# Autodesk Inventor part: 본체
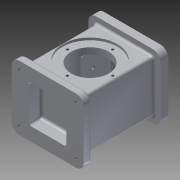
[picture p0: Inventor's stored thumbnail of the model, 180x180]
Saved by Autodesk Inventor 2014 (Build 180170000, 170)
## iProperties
Created: 2017-08
Part Number: 본체
Material: 알루미늄 6061
Document SubType Name: Modeling
Designer: user
Density: 2.71 g/cm^3
Appearance: 알루미늄 - 평지
Mass: 874.034 g
Surface Area: 646.55 cm^2
Volume: 322.522 cm^3
Author: user
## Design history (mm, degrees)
sketch "스케치1"
  geometry: L1 (46, -41)-(-46, -41); L2 (-46, -41)-(-46, 41); L3 (-46, 41)-(46, 41); L4 (46, 41)-(46, -41); L5 (46, -41)-(-46, 41); L6 (-46, -41)-(46, 41); 1 further point
  constraints: 12 end point, 2 midpoint, 2 parallel, 1 horizontal, 1 perpendicular
  dimensions: "d0" = 92 distance of L2.end L3.end; "d1" = 82 distance of L1.end L2.end
extrude "돌출1" new body sketch "스케치1" distance "d2" = 10; taper "d3" = 0 deg
sketch "스케치2"
  geometry: L1 (37, -33)-(-37, -33); L2 (-37, -33)-(-37, 33); L3 (-37, 33)-(37, 33); L4 (37, 33)-(37, -33); L5 (37, -33)-(-37, 33); L6 (-37, -33)-(37, 33); 1 further point
  constraints: 12 end point, 2 midpoint, 2 parallel, 1 horizontal, 1 perpendicular
  dimensions: "d4" = 74 distance of L2.end L3.end; "d5" = 66 distance of L1.end L2.end
extrude "돌출2" join sketch "스케치2" distance "d6" = 98; taper "d7" = 0 deg
sketch "스케치3"
  geometry: L1 (-37, -33)-(37, -33) reference; L2 (37, -33)-(37, 33) reference; L3 (37, 33)-(-37, 33) reference; L4 (-37, 33)-(-37, -33) reference; L5 (46, -41)-(-46, -41); L6 (-46, -41)-(-46, 41); L7 (-46, 41)-(46, 41); L8 (46, 41)-(46, -41); L9 (46, -41)-(-46, 41); L10 (-46, -41)-(46, 41); 1 further point
  constraints: 12 end point, 2 midpoint, 2 parallel, 1 horizontal, 1 perpendicular
  dimensions: "d8" = 92 distance of L6.end L7.end; "d9" = 82 distance of L5.end L6.end
extrude "돌출3" join sketch "스케치3" distance "d10" = 10; taper "d11" = 0 deg
node "작업 평면1"
sketch "스케치4"
  geometry: L1 (74, 0)-(74, -10) reference; L2 (74, -10)-(-8, -10) reference; L3 (-8, -10)-(-8, 0) reference; L4 (-8, 0)-(0, 0) reference; L5 (0, 0)-(0, 88) reference; L6 (0, 88)-(-8, 88) reference; L7 (-8, 88)-(-8, 98) reference; L8 (-8, 98)-(74, 98) reference; L9 (74, 98)-(74, 88) reference; L10 (74, 88)-(66, 88) reference; L11 (66, 88)-(66, 0) reference; L12 (66, 0)-(74, 0) reference; L13 (0, 79)-(3, 79); L14 (3, 79)-(3, 68); L15 (3, 68)-(63, 68); L16 (63, 68)-(63, 79); L17 (63, 79)-(66, 79); L18 (0, 44)-(66, 44); L19 (0, 79)-(0, 44); L20 (66, 79)-(66, 44); 1 further point
  constraints: 16 end point, 4 perpendicular, 3 parallel, 2 collinear, 2 midpoint, 2 point on line
  dimensions: "d12" = 3 distance of L13.start L13.end; "d13" = 3 distance of L16.end L17.end; "d15" = 54 distance from line of L2 L18.start; "d16" = 70 diameter of L13 L18; "d17" = 48 diameter of L15 L18
revolve "회전1" sketch "스케치4" stored, may be unused: angle "d18" = 90 deg
sketch "스케치5"
  geometry: L1 (24, -24)-(-24, -24); L2 (-24, -24)-(-24, 24); L3 (-24, 24)-(24, 24); L4 (24, 24)-(24, -24); L5 (24, -24)-(-24, 24); L6 (-24, -24)-(24, 24); 1 further point
  constraints: 12 end point, 2 midpoint, 2 parallel, 1 horizontal, 1 perpendicular
  dimensions: "d19" = 48 distance of L2.end L3.end; "d20" = 48 distance of L1.end L2.end
extrude "돌출4" cut sketch "스케치5" distance "d21" = 16; taper "d22" = 0 deg
sketch "스케치6"
  geometry: L1 (26, -26)-(-26, -26); L2 (-26, -26)-(-26, 26); L3 (-26, 26)-(26, 26); L4 (26, 26)-(26, -26); L5 (26, -26)-(-26, 26); L6 (-26, -26)-(26, 26); L7 (22, -22)-(-22, -22); L8 (-22, -22)-(-22, 22); L9 (-22, 22)-(22, 22); L10 (22, 22)-(22, -22); L11 (22, -22)-(-22, 22); L12 (-22, -22)-(22, 22); 1 further point
  constraints: 24 end point, 4 midpoint, 4 parallel, 2 horizontal, 2 perpendicular
  dimensions: "d23" = 52 distance of L2.end L3.end; "d24" = 52 distance of L1.end L2.end; "d25" = 44 distance of L8.end L9.end; "d26" = 44 distance of L7.end L8.end
extrude "돌출5" cut sketch "스케치6" distance "d27" = 82; taper "d28" = 0 deg
extrude "돌출6" cut sketch "스케치6" distance "d29" = 8; taper "d30" = 0 deg
sketch "스케치8" dims "d32" = 58
  geometry: C1 r 24 at (0, 0) reference; 3 further points
  constraints: 1 coincident, 1 vertical alignment, 2 other
hole "구멍1" sketch "스케치8" at (0, 29) diameter "d33" = 3.242; stored, may be unused: countersink angle "d37" = 90 deg, drill point angle "d39" = 118 deg; dims "d34" = 4, "d35" = 4, "d36" = 2, "d38" = 6
fillet "모깎기1" dims "d43" = 10
sketch "스케치9"
  geometry: A1 r 10 centre (-36, 31) between (-36, 41) and (-46, 31) reference; A2 r 10 centre (-36, -31) between (-46, -31) and (-36, -41) reference; A3 r 10 centre (36, -31) between (36, -41) and (46, -31) reference; A4 r 10 centre (36, 31) between (46, 31) and (36, 41) reference; 5 further points
  constraints: 4 coincident
hole "구멍3" sketch "스케치9" at (-36, 31), (36, 31), (36, -31), (-36, -31) diameter "d51" = 3.242; stored, may be unused: countersink angle "d55" = 90 deg, drill point angle "d57" = 118 deg; dims "d52" = 4, "d53" = 4, "d54" = 2, "d56" = 6
sketch "스케치10"
  geometry: A1 r 10 centre (-36, 31) between (-36, 41) and (-46, 31) reference; A2 r 10 centre (-36, -31) between (-46, -31) and (-36, -41) reference; A3 r 10 centre (36, -31) between (36, -41) and (46, -31) reference; A4 r 10 centre (36, 31) between (46, 31) and (36, 41) reference; 5 further points
  constraints: 4 coincident
hole "구멍4" sketch "스케치10" at (-36, 31), (36, 31), (36, -31), (-36, -31) diameter "d58" = 3.242; stored, may be unused: countersink angle "d62" = 90 deg, drill point angle "d64" = 118 deg; dims "d59" = 4, "d60" = 4, "d61" = 2, "d63" = 6
fillet "모깎기2" dims "d65" = 3
fillet "모깎기3" dims "d66" = 3
chamfer "모따기1" distance "d67" = 1; stored, may be unused: second distance "d68" = 2, angle "d69" = 45 deg
sketch "스케치11"
  geometry: L1 (-60, 0)-(-60, 82) reference; L2 (-30, 109.604)-(-30, -43.009); L3 (1, -13)-(-61, -13) reference; 3 further points
  constraints: 2 end point, 2 point on line, 1 parallel
  dimensions: "d70" = 38 distance from line of L3 point (-30, 25); "d71" = 42 distance of point (-30, 25) point (-30, 67)
hole "구멍5" sketch "스케치11" at (-30, 67), (-30, 25) diameter "d72" = 4.134; stored, may be unused: countersink angle "d76" = 90 deg, drill point angle "d78" = 0 deg; dims "d73" = 15, "d74" = 4, "d75" = 2, "d77" = 6
node "작업 평면3"
sketch "스케치12"
  geometry: L1 (18.458, -2.304)-(53.498, -2.304); L2 (53.498, -2.304)-(53.498, -7.107); L3 (53.498, -7.107)-(18.458, -7.107); L4 (18.458, -7.107)-(18.458, -2.304); 2 further points
  constraints: 2 other
feature "엠보싱1" sketch "스케치12" dims "d0" = 92, "d1" = 82, "d81" = 0.5, "d82" = 0
node "솔리드1"
pattern_circular "원형 패턴1" dims angle "d41" = 360 deg
mirror "대칭1"
node "절단 모서리 투영1"
other parameters: "d79" = 37.5
